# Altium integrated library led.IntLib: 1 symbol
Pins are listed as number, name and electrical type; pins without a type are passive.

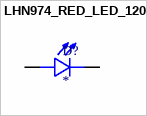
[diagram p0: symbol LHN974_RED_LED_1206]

## LHN974_RED_LED_1206
designator D?
2.6 V Red LED SMD; MF: Osram; MP: LHN974 RED LED 1206
footprint LEDC3216X120N
pins: NEG, POS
